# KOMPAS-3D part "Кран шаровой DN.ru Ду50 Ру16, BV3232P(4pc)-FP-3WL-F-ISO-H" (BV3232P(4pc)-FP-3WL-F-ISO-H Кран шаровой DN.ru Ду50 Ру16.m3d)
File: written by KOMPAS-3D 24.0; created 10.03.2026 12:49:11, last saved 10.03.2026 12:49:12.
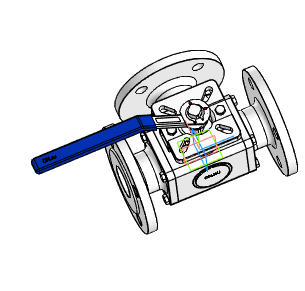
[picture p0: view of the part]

Document properties: Автор: R2D2; Полное имя файла: BV3232P(4pc)-FP-3WL-F-ISO-H Кран шаровой DN.ru Ду50 Ру16.cdw

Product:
- Part/product: Кран шаровой DN.ru Ду50 Ру16  | designation BV3232P(4pc)-FP-3WL-F-ISO-H
    Масса: 17.95
    Раздел спецификации: Прочие изделия
    Форматы листов документа: A3
    Примечание: D160-36360

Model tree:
1. Операция без истории:1

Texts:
  BV3232P(4pc)-FP-3WL-F-ISO-H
